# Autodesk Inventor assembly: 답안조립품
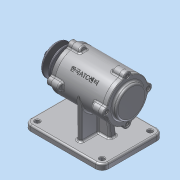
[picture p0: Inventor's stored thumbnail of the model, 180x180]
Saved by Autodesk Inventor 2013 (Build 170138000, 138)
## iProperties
Created: 2015-12
Part Number: 답안조립품
Document SubType Name: Assembly
Designer: dgall
Author: dgall
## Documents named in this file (11)
- C:\Users\dgall\Desktop\451207V1030\답안조립품.iam
- C:\Users\dgall\Desktop\451207V1030\본체.ipt
- C:\Users\dgall\Desktop\451207V1030\베어링 6204.ipt
- C:\Users\dgall\Desktop\451207V1030\오일실.ipt
- C:\Users\dgall\Desktop\451207V1030\커버.ipt
- C:\Users\dgall\Desktop\451207V1030\커버2.ipt
- C:\Users\dgall\Desktop\451207V1030\볼트 M4 x 12.ipt
- C:\Users\dgall\Desktop\451207V1030\V-벨트풀리.ipt
- C:\Users\dgall\Desktop\451207V1030\너트 M12x1.25.ipt
- C:\Users\dgall\Desktop\451207V1030\축.ipt
- C:\Users\dgall\Desktop\451207V1030\키(4 x 4 x 12).ipt
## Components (6 placed, 5 different names)
1. KS B 2023 6204 - 20 x 47 x 14:1
2. KS B 2023 6204 - 20 x 47 x 14:2
3. KS B 2804 D D - 20 32 8:1
4. V-벨트풀리:1
5. KS B 1012 클래스 1 일반 - 미터 M12x1.25:1
6. KS B 1311 (I) 4 x 4 x 12:1 — 각도:1
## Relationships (1: Angle 1)
- 각도:1 [Angle]: KS B 1311 (I) 4 x 4 x 12:1
